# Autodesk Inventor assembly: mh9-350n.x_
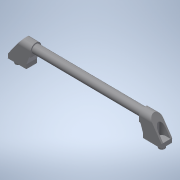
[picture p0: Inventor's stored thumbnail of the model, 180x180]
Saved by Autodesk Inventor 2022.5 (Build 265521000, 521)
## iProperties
Part Number: mh9-350n.x_
Material: 一般
Document SubType Name: Assembly
Designer: ImaoCorp
Sending System: SOLIDWORKS 2017-2017317
MC: AMD64
MC_MODEL: Intel64 Family 6 Model 60 Stepping 3, GenuineIntel
OS: Windows_NT
FRU: Parasolid Version 29.0, build 201,  4-17-2017
FORMAT: text
GUISE: transmit
KEY: mh9-350n
FILE: mh9-350n.x_t
DATE: Fri Jul 26 11:47:31 2019
Author: ImaoCorp
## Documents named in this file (4)
- X:\14_SW2022-Inv2022\00_全2023-1023新製品(TCC)まで\m\mh9-350n\MH9-350N.iam
- X:\14_SW2022-Inv2022\00_全2023-1023新製品(TCC)まで\m\mh9-350n\mh9-350n_01.ipt
- X:\14_SW2022-Inv2022\00_全2023-1023新製品(TCC)まで\m\mh9-350n\mh9-350n_02.ipt
- X:\14_SW2022-Inv2022\00_全2023-1023新製品(TCC)まで\m\mh9-350n\mh9-350n_03.ipt
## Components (3 placed, 3 different names)
1. mh9-350n_01
2. mh9-350n_02
3. mh9-350n_03
